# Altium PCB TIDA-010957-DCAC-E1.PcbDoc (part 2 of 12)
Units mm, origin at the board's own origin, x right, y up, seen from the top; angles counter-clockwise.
Board outline 300 x 300 mm, 4 copper layers (Top Layer, Layer 1, Layer 2, Bottom Layer), stack 1.787 mm thick; 1159 components, 619 nets, 3431 pads, 2942 vias.
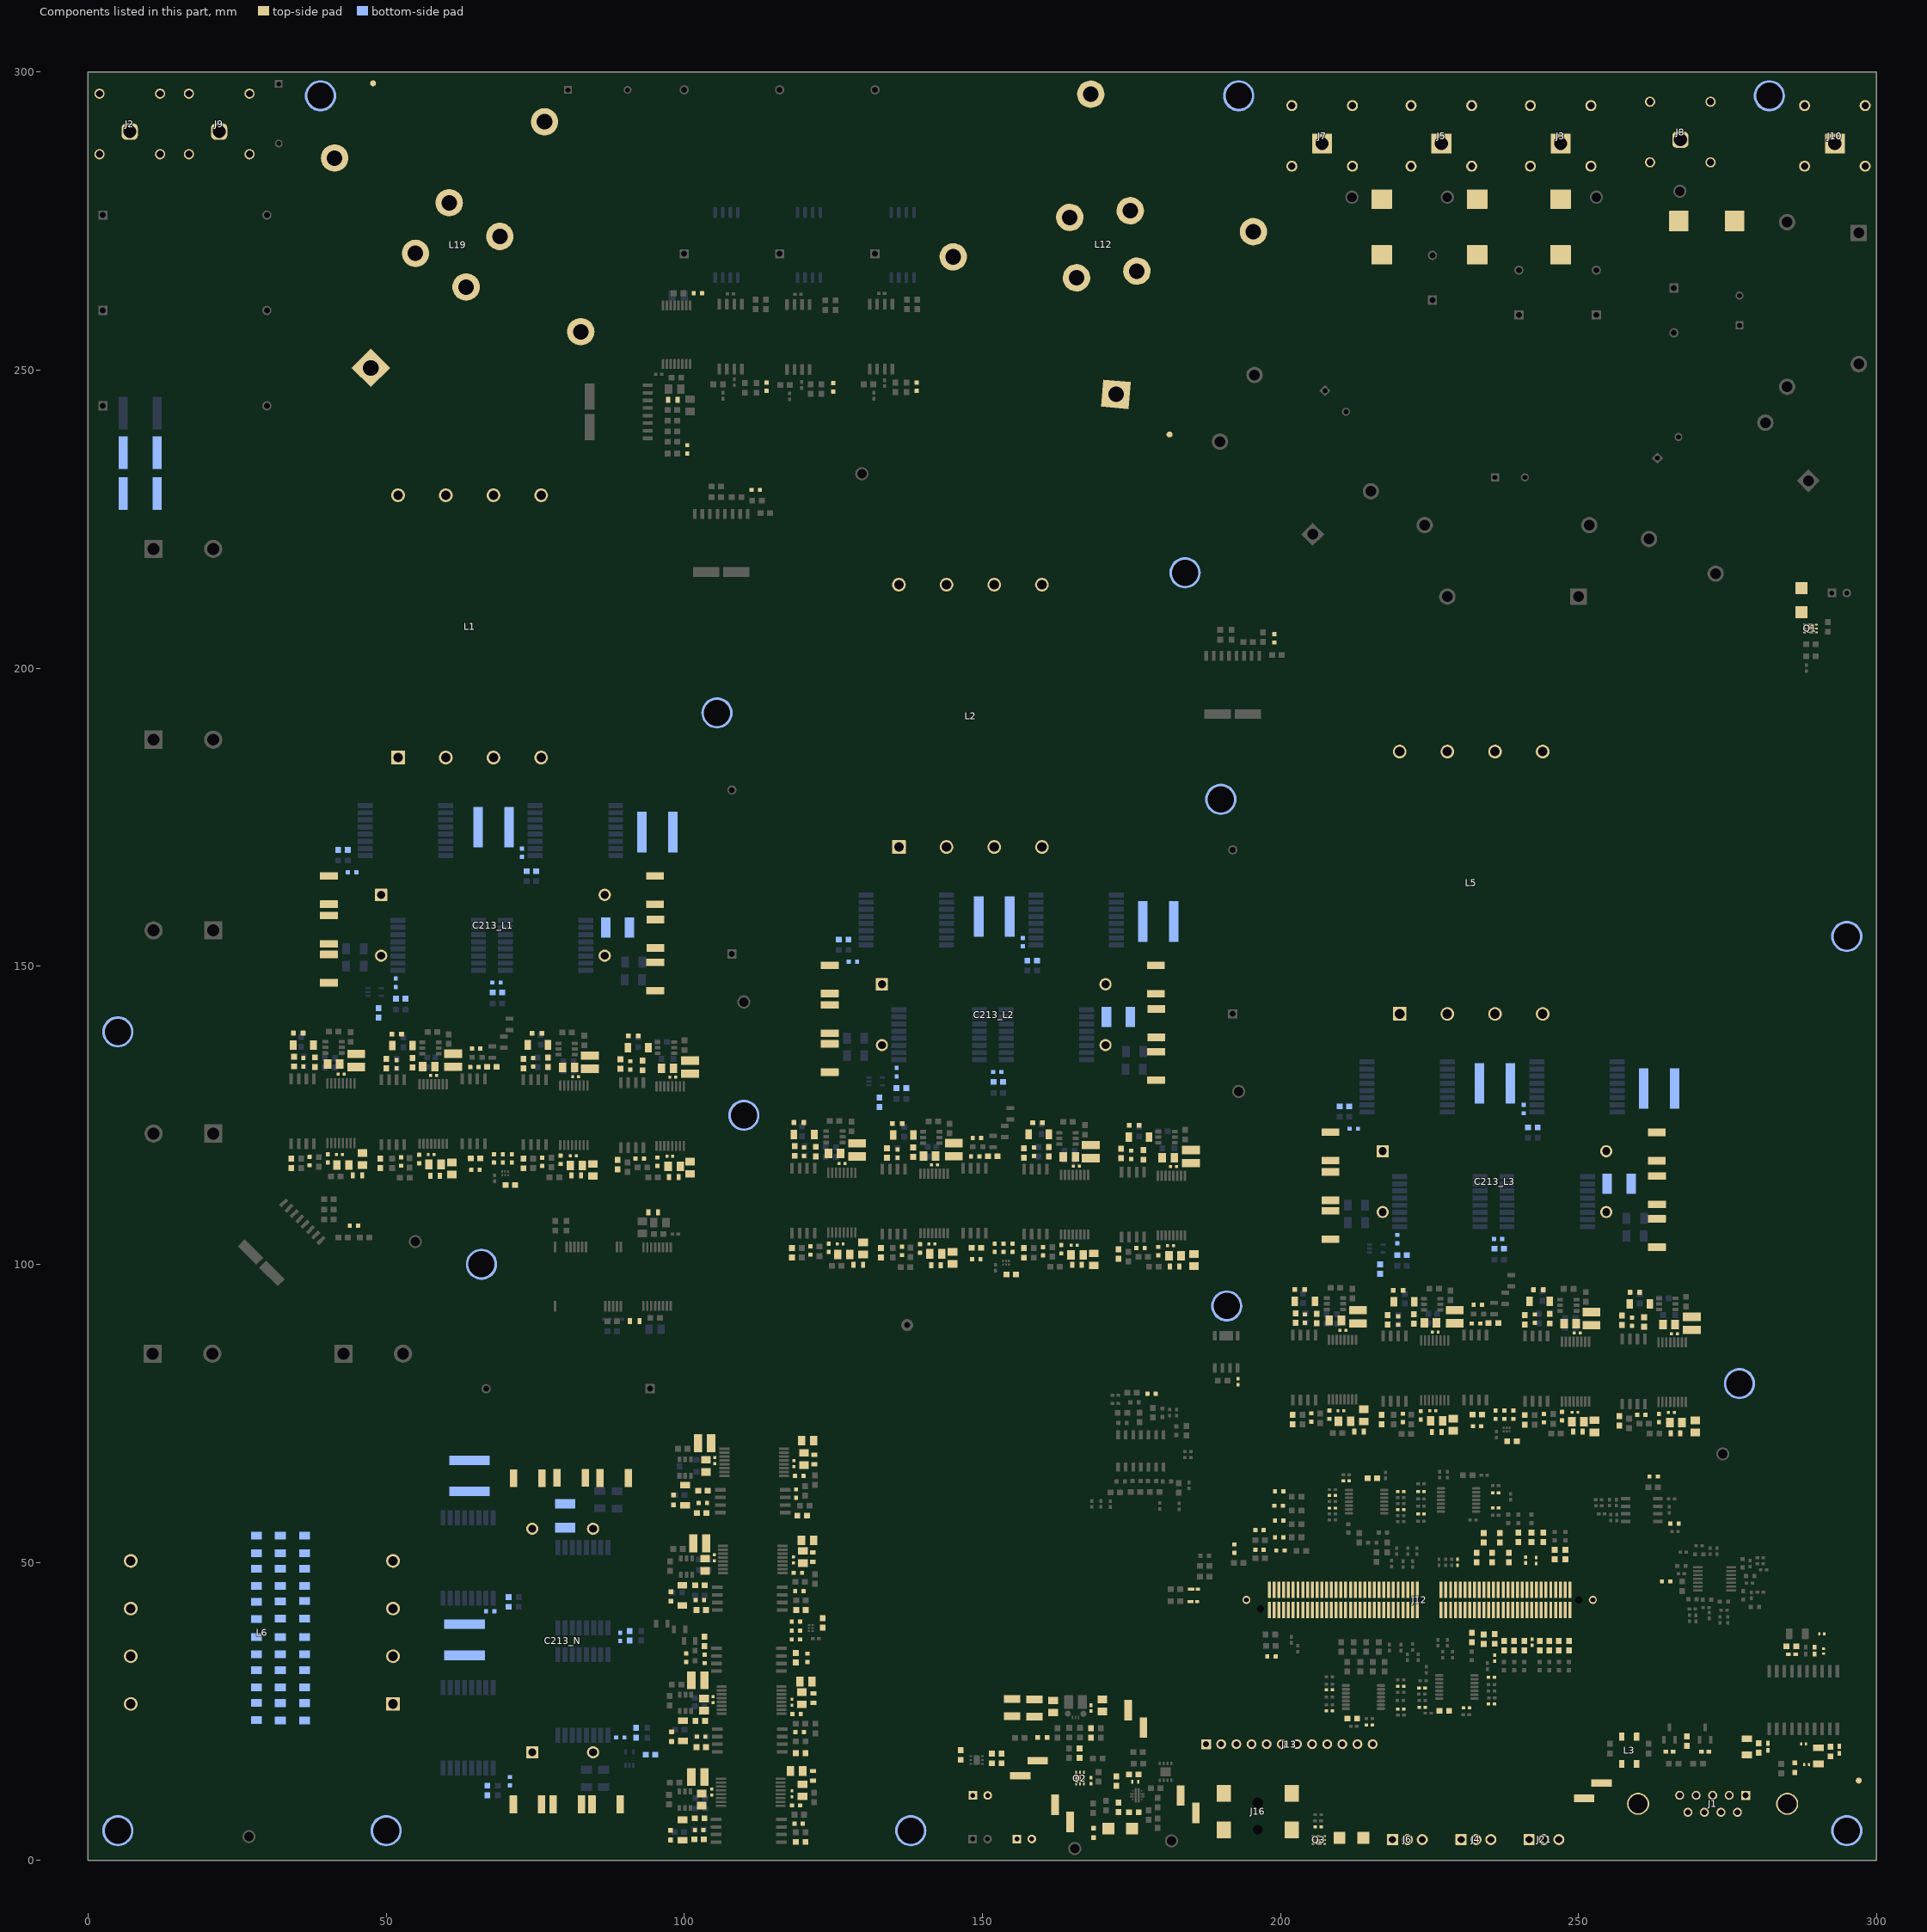
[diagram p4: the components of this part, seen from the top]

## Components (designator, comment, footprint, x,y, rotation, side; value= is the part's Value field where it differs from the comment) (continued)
C109 "GRM1555C1H101JA01D" 0402L 223.6,61.9 r180 top value=100pF
C110 "GRM1555C1H101JA01D" 0402L 223.6,58.15 r180 top value=100pF
C111 "GRM1555C1H101JA01D" 0402L 236.1,59.15 r0 top value=100pF
C112 "GRM1555C1H101JA01D" 0402L 236.1,61.65 r0 top value=100pF
C113 "06033C104JAT2A" 0603 215.4,64.1 r180 top value=0.1uF
C114 "06033C104JAT2A" 0603 212.066,23.781 r0 top value=0.1uF
C115 "GRM1555C1H101JA01D" 0402L 211.048,63.675 r180 top value=100pF
C116 "GRM1555C1H101JA01D" 0402L 208.7,61.2 r180 top value=100pF
C117 "GRM1555C1H101JA01D" 0402L 208.7,59.1 r180 top value=100pF
C118 "GRM1555C1H101JA01D" 0402L 220.2,58.85 r0 top value=100pF
C119 "GRM1555C1H101JA01D" 0402L 220.2,61.85 r0 top value=100pF
C120 "GRM1555C1H101JA01D" 0402L 214.9,22.7 r180 top value=100pF
C121 "GRM1555C1H101JA01D" 0402L 220.2,25.4 r0 top value=100pF
C122 "GRM1555C1H101JA01D" 0402L 220.2,29.2 r0 top value=100pF
C123 "GRM1555C1H101JA01D" 0402L 208.2,28.6 r180 top value=100pF
C124 "GRM1555C1H101JA01D" 0402L 208.2,25.1 r180 top value=100pF
C125 "06033C104JAT2A" 0603 227.5,25.1 r0 top value=0.1uF
C126 "GRM1555C1H101JA01D" 0402L 231.2,25.6 r180 top value=100pF
C127 "GRM1555C1H101JA01D" 0402L 235.393,26.25 r0 top value=100pF
C128 "GRM1555C1H101JA01D" 0402L 235.4,30.7 r0 top value=100pF
C129 "GRM1555C1H101JA01D" 0402L 223.75,28.9 r180 top value=100pF
C130 "GRM1555C1H101JA01D" 0402L 223.8,25.7 r180 top value=100pF
C131 "C1608X7R1V105K080AC" 0603 175.379,14.45 r180 top value=1uF
C132 "GCM155R71H104KE02D" 0402S 175.651,13.186 r180 top value=0.1uF
C133 "C1608X7R1V105K080AC" 0603 175.427,8.094 r180 top value=1uF
C134 "GRM188R72A272KA01D" 0603 172.851,8.9 r270 top value=2700pF
C135 "C0603X332K5RACTU" 0603 172.479,13.325 r90 top value=3300pF
C136 "GRM155R71E104KE14D" 0402L 168.232,13.384 r90 top value=0.1uF
C137 "GRM1885C2A220JA01D" 0603 168.207,21.396 r90 top value=22pF
C138 "06033C104JAT2A" 0603 153.2,17.1 r270 top value=0.1uF
C139 "GRM32ER71A476KE15L" 1210_270 158.733,25.569 r270 top value=47uF
C140 "GRM32ER71A476KE15L" 1210_270 154.983,25.615 r270 top value=47uF
C141 "EMK212BB7106KG-T" 0805_HV 170.133,25.994 r90 top value=10uF
C142 "GCM155R71H104KE02D" 0402L 168.207,25.544 r270 top value=0.1uF
C143 "GRM21BZ71A226ME15L" 0805_HV 161.883,25.819 r270 top value=22uF
C144 "EMK107BB7225KA-T" 0603 151.6,17.1 r270 top value=2.2uF
C145 "EMK107BB7225KA-T" 0603 146.35,17.677 r270 top value=2.2uF
C146 "C0603C103K4RACTU" 0603 166.32,17.971 r90 top value=0.01uF
C147 "GCM188R71C105KA64J" 0603 285.7,35.9 r180 top value=1uF
C148 "GRM155R71H103KA88D" 0402 285.8,34.6 r180 top value=0.01uF
C149 "GRM155R71E104KE14D" 0402 293.75,18.55 r270 top value=0.1uF
C150 "GCM188R71C105KA64J" 0603 292.25,18.25 r270 top value=1uF
C151 "CL31B106KBHNNNE" 1206_180L 290.25,17.55 r270 top value=10uF
C152 "GRM155R71E104KE14D" 0402 289.6,35.2 r90 top value=0.1uF
C153 "GRM155R71H103KA88D" 0402 281.75,19.05 r90 top value=0.01uF
C154 "GCM188R71C105KA64J" 0603 280.243,18.855 r90 top value=1uF
C155 "CL31B106KBHNNNE" 1206_180L 278.25,19.05 r90 top value=10uF
C156 "C1005C0G1H680J050BA" 0402 265.25,18.25 r0 top value=68pF
C157 "C0603X472K5RACTU" 0603 268.2,20 r270 top value=4700pF
C158 "C1005C0G1H680J050BA" 0402 271.25,18.25 r180 top value=68pF
C159 "CGA3E2C0G1H331J080AA" FP-CGA3E2C0G1H331J080AA_0603-MFG 199.8,61.9 r0 top value=330pF
C160 "CGA3E2C0G1H331J080AA" FP-CGA3E2C0G1H331J080AA_0603-MFG 199.7,59.5 r0 top value=330pF
C161 "CGA3E2C0G1H331J080AA" FP-CGA3E2C0G1H331J080AA_0603-MFG 199.8,57 r0 top value=330pF
C162 "CGA3E2C0G1H331J080AA" FP-CGA3E2C0G1H331J080AA_0603-MFG 199.8,54.2 r0 top value=330pF
C186_L1 "06033C104JAT2A" 0603 88.825,116.73 r270 top value=0.1uF (schematic designator C186)
C186_L2 "06033C104JAT2A" 0603 172.825,101.73 r270 top value=0.1uF (schematic designator C186)
C186_L3 "06033C104JAT2A" 0603 256.825,73.73 r270 top value=0.1uF (schematic designator C186)
C186_N "06033C104JAT2A" 0603 119.77,57.825 r0 top value=0.1uF (schematic designator C186)
C187_L1 "06033C104JAT2A" 0603 89.3,133.594 r90 top value=0.1uF (schematic designator C187)
C187_L2 "06033C104JAT2A" 0603 173.3,118.594 r90 top value=0.1uF (schematic designator C187)
C187_L3 "06033C104JAT2A" 0603 257.3,90.594 r90 top value=0.1uF (schematic designator C187)
C187_N "06033C104JAT2A" 0603 102.906,58.3 r180 top value=0.1uF (schematic designator C187)
C188_L1 "CGA3E2C0G1H331J080AA" FP-CGA3E2C0G1H331J080AA_0603-MFG 72.801,169.047 r270 bottom value=330pF (schematic designator C188)
C188_L2 "CGA3E2C0G1H331J080AA" FP-CGA3E2C0G1H331J080AA_0603-MFG 156.801,154.047 r270 bottom value=330pF (schematic designator C188)
C188_L3 "CGA3E2C0G1H331J080AA" FP-CGA3E2C0G1H331J080AA_0603-MFG 240.801,126.047 r270 bottom value=330pF (schematic designator C188)
C188_N "CGA3E2C0G1H331J080AA" FP-CGA3E2C0G1H331J080AA_0603-MFG 67.453,41.801 r0 bottom value=330pF (schematic designator C188)
C189_L1 "CGA3E2C0G1H331J080AA" FP-CGA3E2C0G1H331J080AA_0603-MFG 90.967,133.366 r270 top value=330pF (schematic designator C189)
C189_L2 "CGA3E2C0G1H331J080AA" FP-CGA3E2C0G1H331J080AA_0603-MFG 174.967,118.366 r270 top value=330pF (schematic designator C189)
C189_L3 "CGA3E2C0G1H331J080AA" FP-CGA3E2C0G1H331J080AA_0603-MFG 258.967,90.366 r270 top value=330pF (schematic designator C189)
C189_N "CGA3E2C0G1H331J080AA" FP-CGA3E2C0G1H331J080AA_0603-MFG 103.134,59.967 r0 top value=330pF (schematic designator C189)
C190_L1 "06033C104JAT2A" 0603 74.351,165.957 r180 bottom value=0.1uF (schematic designator C190)
C190_L2 "06033C104JAT2A" 0603 158.351,150.957 r180 bottom value=0.1uF (schematic designator C190)
C190_L3 "06033C104JAT2A" 0603 242.351,122.957 r180 bottom value=0.1uF (schematic designator C190)
C190_N "06033C104JAT2A" 0603 70.543,43.351 r270 bottom value=0.1uF (schematic designator C190)
C191_L1 "CGA3E2C0G1H331J080AA" FP-CGA3E2C0G1H331J080AA_0603-MFG 92.538,117.738 r180 top value=330pF (schematic designator C191)
C191_L2 "CGA3E2C0G1H331J080AA" FP-CGA3E2C0G1H331J080AA_0603-MFG 176.538,102.738 r180 top value=330pF (schematic designator C191)
C191_L3 "CGA3E2C0G1H331J080AA" FP-CGA3E2C0G1H331J080AA_0603-MFG 260.538,74.738 r180 top value=330pF (schematic designator C191)
C191_N "CGA3E2C0G1H331J080AA" FP-CGA3E2C0G1H331J080AA_0603-MFG 118.762,61.538 r270 top value=330pF (schematic designator C191)
C192_L1 "GRT31CR61H106KE01L" 1206_180 92.275,136.345 r180 top value=10uF (schematic designator C192)
C192_L2 "GRT31CR61H106KE01L" 1206_180 176.275,121.345 r180 top value=10uF (schematic designator C192)
C192_L3 "GRT31CR61H106KE01L" 1206_180 260.275,93.345 r180 top value=10uF (schematic designator C192)
C192_N "GRT31CR61H106KE01L" 1206_180 100.155,61.275 r270 top value=10uF (schematic designator C192)
C193_L1 "885012205063" WCAP-CSGP_0402_L1W0.5H0.5 98.088,131.367 r0 top (schematic designator C193)
C193_L2 "885012205063" WCAP-CSGP_0402_L1W0.5H0.5 182.088,116.367 r0 top (schematic designator C193)
C193_L3 "885012205063" WCAP-CSGP_0402_L1W0.5H0.5 266.088,88.367 r0 top (schematic designator C193)
C193_N "885012205063" WCAP-CSGP_0402_L1W0.5H0.5 105.133,67.088 r90 top (schematic designator C193)
C194_L1 "GRM21BZ71A226ME15L" 0805_HV 97.188,132.869 r180 top value=22uF (schematic designator C194)
C194_L2 "GRM21BZ71A226ME15L" 0805_HV 181.188,117.869 r180 top value=22uF (schematic designator C194)
C194_L3 "GRM21BZ71A226ME15L" 0805_HV 265.188,89.869 r180 top value=22uF (schematic designator C194)
C194_N "GRM21BZ71A226ME15L" 0805_HV 103.631,66.188 r270 top value=22uF (schematic designator C194)
C195_L1 "06033C104JAT2A" 0603 93,133.348 r270 top value=0.1uF (schematic designator C195)
C195_L2 "06033C104JAT2A" 0603 177,118.348 r270 top value=0.1uF (schematic designator C195)
C195_L3 "06033C104JAT2A" 0603 261,90.348 r270 top value=0.1uF (schematic designator C195)
C195_N "06033C104JAT2A" 0603 103.152,62 r0 top value=0.1uF (schematic designator C195)
C196_L1 "CGA3E2C0G1H331J080AA" FP-CGA3E2C0G1H331J080AA_0603-MFG 95.497,117.205 r90 top value=330pF (schematic designator C196)
C196_L2 "CGA3E2C0G1H331J080AA" FP-CGA3E2C0G1H331J080AA_0603-MFG 179.497,102.205 r90 top value=330pF (schematic designator C196)
C196_L3 "CGA3E2C0G1H331J080AA" FP-CGA3E2C0G1H331J080AA_0603-MFG 263.497,74.205 r90 top value=330pF (schematic designator C196)
C196_N "CGA3E2C0G1H331J080AA" FP-CGA3E2C0G1H331J080AA_0603-MFG 119.295,64.497 r180 top value=330pF (schematic designator C196)
C197_L1 "GRM21BZ71A226ME15L" 0805_HV 101,116.188 r90 top value=22uF (schematic designator C197)
C197_L2 "GRM21BZ71A226ME15L" 0805_HV 185.5,100.7 r90 top value=22uF (schematic designator C197)
C197_L3 "GRM21BZ71A226ME15L" 0805_HV 269.6,72.8 r90 top value=22uF (schematic designator C197)
C197_N "GRM21BZ71A226ME15L" 0805_HV 120.7,70.4 r180 top value=22uF (schematic designator C197)
C198_L1 "GRM21BZ71A226ME15L" 0805_HV 98.338,116.43 r0 top value=22uF (schematic designator C198)
C198_L2 "GRM21BZ71A226ME15L" 0805_HV 182.338,101.43 r0 top value=22uF (schematic designator C198)
C198_L3 "GRM21BZ71A226ME15L" 0805_HV 266.338,73.43 r0 top value=22uF (schematic designator C198)
C198_N "GRM21BZ71A226ME15L" 0805_HV 120.07,67.338 r90 top value=22uF (schematic designator C198)
C199_L1 "885012205051" WCAP-CSGP_0402_L1W0.5H0.5 97.588,118.13 r180 top (schematic designator C199)
C199_L2 "885012205051" WCAP-CSGP_0402_L1W0.5H0.5 181.588,103.13 r180 top (schematic designator C199)
C199_L3 "885012205051" WCAP-CSGP_0402_L1W0.5H0.5 265.588,75.13 r180 top (schematic designator C199)
C199_N "885012205051" WCAP-CSGP_0402_L1W0.5H0.5 118.37,66.588 r270 top (schematic designator C199)
C200_L1 "06033C104JAT2A" 0603 73.005,116.908 r270 top value=0.1uF (schematic designator C200)
C200_L2 "06033C104JAT2A" 0603 157.005,101.908 r270 top value=0.1uF (schematic designator C200)
C200_L3 "06033C104JAT2A" 0603 241.005,73.908 r270 top value=0.1uF (schematic designator C200)
C200_N "06033C104JAT2A" 0603 119.592,42.005 r0 top value=0.1uF (schematic designator C200)
C201_L1 "06033C104JAT2A" 0603 73.005,133.666 r90 top value=0.1uF (schematic designator C201)
C201_L2 "06033C104JAT2A" 0603 157.005,118.666 r90 top value=0.1uF (schematic designator C201)
C201_L3 "06033C104JAT2A" 0603 241.005,90.666 r90 top value=0.1uF (schematic designator C201)
C201_N "06033C104JAT2A" 0603 102.834,42.005 r180 top value=0.1uF (schematic designator C201)
C202_L1 "CGA3E2C0G1H331J080AA" FP-CGA3E2C0G1H331J080AA_0603-MFG 68.507,147.25 r0 bottom value=330pF (schematic designator C202)
C202_L2 "CGA3E2C0G1H331J080AA" FP-CGA3E2C0G1H331J080AA_0603-MFG 152.507,132.25 r0 bottom value=330pF (schematic designator C202)
C202_L3 "CGA3E2C0G1H331J080AA" FP-CGA3E2C0G1H331J080AA_0603-MFG 236.507,104.25 r0 bottom value=330pF (schematic designator C202)
C202_N "CGA3E2C0G1H331J080AA" FP-CGA3E2C0G1H331J080AA_0603-MFG 89.25,37.507 r90 bottom value=330pF (schematic designator C202)
C203_L1 "CGA3E2C0G1H331J080AA" FP-CGA3E2C0G1H331J080AA_0603-MFG 74.66,133.882 r270 top value=330pF (schematic designator C203)
C203_L2 "CGA3E2C0G1H331J080AA" FP-CGA3E2C0G1H331J080AA_0603-MFG 158.66,118.882 r270 top value=330pF (schematic designator C203)
C203_L3 "CGA3E2C0G1H331J080AA" FP-CGA3E2C0G1H331J080AA_0603-MFG 242.66,90.882 r270 top value=330pF (schematic designator C203)
C203_N "CGA3E2C0G1H331J080AA" FP-CGA3E2C0G1H331J080AA_0603-MFG 102.618,43.66 r0 top value=330pF (schematic designator C203)
C204_L1 "06033C104JAT2A" 0603 68.682,145.625 r180 bottom value=0.1uF (schematic designator C204)
C204_L2 "06033C104JAT2A" 0603 152.682,130.625 r180 bottom value=0.1uF (schematic designator C204)
C204_L3 "06033C104JAT2A" 0603 236.682,102.625 r180 bottom value=0.1uF (schematic designator C204)
C204_N "06033C104JAT2A" 0603 90.875,37.682 r270 bottom value=0.1uF (schematic designator C204)
C205_L1 "CGA3E2C0G1H331J080AA" FP-CGA3E2C0G1H331J080AA_0603-MFG 76.18,117.18 r90 top value=330pF (schematic designator C205)
C205_L2 "CGA3E2C0G1H331J080AA" FP-CGA3E2C0G1H331J080AA_0603-MFG 160.18,102.18 r90 top value=330pF (schematic designator C205)
C205_L3 "CGA3E2C0G1H331J080AA" FP-CGA3E2C0G1H331J080AA_0603-MFG 244.18,74.18 r90 top value=330pF (schematic designator C205)
C205_N "CGA3E2C0G1H331J080AA" FP-CGA3E2C0G1H331J080AA_0603-MFG 119.32,45.18 r180 top value=330pF (schematic designator C205)
C206_L1 "CGA3E2C0G1H331J080AA" FP-CGA3E2C0G1H331J080AA_0603-MFG 68.075,117.763 r270 top value=330pF (schematic designator C206)
C206_L2 "CGA3E2C0G1H331J080AA" FP-CGA3E2C0G1H331J080AA_0603-MFG 152.075,102.763 r270 top value=330pF (schematic designator C206)
C206_L3 "CGA3E2C0G1H331J080AA" FP-CGA3E2C0G1H331J080AA_0603-MFG 236.075,74.763 r270 top value=330pF (schematic designator C206)
C206_N "CGA3E2C0G1H331J080AA" FP-CGA3E2C0G1H331J080AA_0603-MFG 118.737,37.075 r0 top value=330pF (schematic designator C206)
C207_L1 "CGA3E2C0G1H331J080AA" FP-CGA3E2C0G1H331J080AA_0603-MFG 71.084,117.763 r270 top value=330pF (schematic designator C207)
C207_L2 "CGA3E2C0G1H331J080AA" FP-CGA3E2C0G1H331J080AA_0603-MFG 155.084,102.763 r270 top value=330pF (schematic designator C207)
C207_L3 "CGA3E2C0G1H331J080AA" FP-CGA3E2C0G1H331J080AA_0603-MFG 239.084,74.763 r270 top value=330pF (schematic designator C207)
C207_N "CGA3E2C0G1H331J080AA" FP-CGA3E2C0G1H331J080AA_0603-MFG 118.737,40.084 r0 top value=330pF (schematic designator C207)
C208_L1 "GRT31CR61H106KE01L" 1206_180 75.455,136.8 r180 top value=10uF (schematic designator C208)
C208_L2 "GRT31CR61H106KE01L" 1206_180 159.455,121.8 r180 top value=10uF (schematic designator C208)
C208_L3 "GRT31CR61H106KE01L" 1206_180 243.455,93.8 r180 top value=10uF (schematic designator C208)
C208_N "GRT31CR61H106KE01L" 1206_180 99.7,44.455 r270 top value=10uF (schematic designator C208)
C209_L1 "CGA3E2C0G1H331J080AA" FP-CGA3E2C0G1H331J080AA_0603-MFG 69.566,117.763 r270 top value=330pF (schematic designator C209)
C209_L2 "CGA3E2C0G1H331J080AA" FP-CGA3E2C0G1H331J080AA_0603-MFG 153.566,102.763 r270 top value=330pF (schematic designator C209)
C209_L3 "CGA3E2C0G1H331J080AA" FP-CGA3E2C0G1H331J080AA_0603-MFG 237.566,74.763 r270 top value=330pF (schematic designator C209)
C209_N "CGA3E2C0G1H331J080AA" FP-CGA3E2C0G1H331J080AA_0603-MFG 118.737,38.566 r0 top value=330pF (schematic designator C209)
C210_L1 "885012205063" WCAP-CSGP_0402_L1W0.5H0.5 81.794,131.467 r0 top (schematic designator C210)
C210_L2 "885012205063" WCAP-CSGP_0402_L1W0.5H0.5 165.794,116.467 r0 top (schematic designator C210)
C210_L3 "885012205063" WCAP-CSGP_0402_L1W0.5H0.5 249.794,88.467 r0 top (schematic designator C210)
C210_N "885012205063" WCAP-CSGP_0402_L1W0.5H0.5 105.033,50.794 r90 top (schematic designator C210)
C211_L1 "GRM21BZ71A226ME15L" 0805_HV 80.6,133.023 r180 top value=22uF (schematic designator C211)
C211_L2 "GRM21BZ71A226ME15L" 0805_HV 164.6,118.023 r180 top value=22uF (schematic designator C211)
C211_L3 "GRM21BZ71A226ME15L" 0805_HV 248.6,90.023 r180 top value=22uF (schematic designator C211)
C211_N "GRM21BZ71A226ME15L" 0805_HV 103.477,49.6 r270 top value=22uF (schematic designator C211)
C212_L1 "06033C104JAT2A" 0603 77.155,133.871 r270 top value=0.1uF (schematic designator C212)
C212_L2 "06033C104JAT2A" 0603 161.155,118.871 r270 top value=0.1uF (schematic designator C212)
C212_L3 "06033C104JAT2A" 0603 245.155,90.871 r270 top value=0.1uF (schematic designator C212)
C212_N "06033C104JAT2A" 0603 102.629,46.155 r0 top value=0.1uF (schematic designator C212)
C213_L1 "B32676G6126K000" FP-B32676G6126K000_RADIAL-MFG 67.911,156.866 r0 top value=12µF (schematic designator C213)
C213_L2 "B32676G6126K000" FP-B32676G6126K000_RADIAL-MFG 151.911,141.866 r0 top value=12µF (schematic designator C213)
C213_L3 "B32676G6126K000" FP-B32676G6126K000_RADIAL-MFG 235.911,113.866 r0 top value=12µF (schematic designator C213)
C213_N "B32676G6126K000" FP-B32676G6126K000_RADIAL-MFG 79.609,36.886 r90 top locked value=12µF (schematic designator C213)
C215_L1 "C1812W104KDRACTU" 1812_254 88.825,156.5 r180 bottom value=0.1uF (schematic designator C215)
C215_L2 "C1812W104KDRACTU" 1812_254 172.825,141.5 r180 bottom value=0.1uF (schematic designator C215)
C215_L3 "C1812W104KDRACTU" 1812_254 256.825,113.5 r180 bottom value=0.1uF (schematic designator C215)
C215_N "C1812W104KDRACTU" 1812_254 80,57.825 r270 bottom value=0.1uF (schematic designator C215)
C216_L1 "C2225C104KFRACTU" 2225 68,173.35 r180 bottom value=0.1uF (schematic designator C216)
C216_L2 "C2225C104KFRACTU" 2225 152,158.35 r180 bottom value=0.1uF (schematic designator C216)
C216_L3 "C2225C104KFRACTU" 2225 236,130.35 r180 bottom value=0.1uF (schematic designator C216)
C216_N "C2225C104KFRACTU" 2225 63.15,37 r270 bottom value=0.1uF (schematic designator C216)
C217_L1 "C2225C104KFRACTU" 2225 95.5,172.5 r0 bottom value=0.1uF (schematic designator C217)
C217_L2 "C2225C104KFRACTU" 2225 179.5,157.5 r0 bottom value=0.1uF (schematic designator C217)
C217_L3 "C2225C104KFRACTU" 2225 263.5,129.5 r0 bottom value=0.1uF (schematic designator C217)
C217_N "C2225C104KFRACTU" 2225 64,64.5 r90 bottom value=0.1uF (schematic designator C217)
C219_L1 "CGA3E2C0G1H331J080AA" FP-CGA3E2C0G1H331J080AA_0603-MFG 79.25,117.53 r90 top value=330pF (schematic designator C219)
C219_L2 "CGA3E2C0G1H331J080AA" FP-CGA3E2C0G1H331J080AA_0603-MFG 163.25,102.53 r90 top value=330pF (schematic designator C219)
C219_L3 "CGA3E2C0G1H331J080AA" FP-CGA3E2C0G1H331J080AA_0603-MFG 247.25,74.53 r90 top value=330pF (schematic designator C219)
C219_N "CGA3E2C0G1H331J080AA" FP-CGA3E2C0G1H331J080AA_0603-MFG 119.07,48.25 r180 top value=330pF (schematic designator C219)
C220_L1 "GRM21BZ71A226ME15L" 0805_HV 84.675,115.817 r90 top value=22uF (schematic designator C220)
C220_L2 "GRM21BZ71A226ME15L" 0805_HV 168.675,100.817 r90 top value=22uF (schematic designator C220)
C220_L3 "GRM21BZ71A226ME15L" 0805_HV 252.675,72.817 r90 top value=22uF (schematic designator C220)
C220_N "GRM21BZ71A226ME15L" 0805_HV 120.683,53.675 r180 top value=22uF (schematic designator C220)
C221_L1 "GRM21BZ71A226ME15L" 0805_HV 81.9,116.588 r0 top value=22uF (schematic designator C221)
C221_L2 "GRM21BZ71A226ME15L" 0805_HV 165.9,101.588 r0 top value=22uF (schematic designator C221)
C221_L3 "GRM21BZ71A226ME15L" 0805_HV 249.9,73.588 r0 top value=22uF (schematic designator C221)
C221_N "GRM21BZ71A226ME15L" 0805_HV 119.912,50.9 r90 top value=22uF (schematic designator C221)
C222_L1 "885012205051" WCAP-CSGP_0402_L1W0.5H0.5 81.394,118.182 r180 top (schematic designator C222)
C222_L2 "885012205051" WCAP-CSGP_0402_L1W0.5H0.5 165.394,103.182 r180 top (schematic designator C222)
C222_L3 "885012205051" WCAP-CSGP_0402_L1W0.5H0.5 249.394,75.182 r180 top (schematic designator C222)
C222_N "885012205051" WCAP-CSGP_0402_L1W0.5H0.5 118.318,50.394 r270 top (schematic designator C222)
C223_L1 "06033C104JAT2A" 0603 70.831,113.292 r0 top value=0.1uF (schematic designator C223)
C223_L2 "06033C104JAT2A" 0603 154.831,98.292 r0 top value=0.1uF (schematic designator C223)
C223_L3 "06033C104JAT2A" 0603 238.831,70.292 r0 top value=0.1uF (schematic designator C223)
C223_N "06033C104JAT2A" 0603 123.208,39.831 r90 top value=0.1uF (schematic designator C223)
C224_L1 "06033C104JAT2A" 0603 49,116.955 r270 top value=0.1uF (schematic designator C224)
C224_L2 "06033C104JAT2A" 0603 133,101.955 r270 top value=0.1uF (schematic designator C224)
C224_L3 "06033C104JAT2A" 0603 217,73.955 r270 top value=0.1uF (schematic designator C224)
C224_N "06033C104JAT2A" 0603 119.545,18 r0 top value=0.1uF (schematic designator C224)
C225_L1 "06033C104JAT2A" 0603 50.008,133.666 r90 top value=0.1uF (schematic designator C225)
C225_L2 "06033C104JAT2A" 0603 134.008,118.666 r90 top value=0.1uF (schematic designator C225)
C225_L3 "06033C104JAT2A" 0603 218.008,90.666 r90 top value=0.1uF (schematic designator C225)
C225_N "06033C104JAT2A" 0603 102.834,19.008 r180 top value=0.1uF (schematic designator C225)
C226_L1 "CGA3E2C0G1H331J080AA" FP-CGA3E2C0G1H331J080AA_0603-MFG 51.622,147.225 r90 bottom value=330pF (schematic designator C226)
C226_L2 "CGA3E2C0G1H331J080AA" FP-CGA3E2C0G1H331J080AA_0603-MFG 135.622,132.225 r90 bottom value=330pF (schematic designator C226)
C226_L3 "CGA3E2C0G1H331J080AA" FP-CGA3E2C0G1H331J080AA_0603-MFG 219.622,104.225 r90 bottom value=330pF (schematic designator C226)
C226_N "CGA3E2C0G1H331J080AA" FP-CGA3E2C0G1H331J080AA_0603-MFG 89.275,20.622 r180 bottom value=330pF (schematic designator C226)
C227_L1 "CGA3E2C0G1H331J080AA" FP-CGA3E2C0G1H331J080AA_0603-MFG 51.764,133.566 r270 top value=330pF (schematic designator C227)
C227_L2 "CGA3E2C0G1H331J080AA" FP-CGA3E2C0G1H331J080AA_0603-MFG 135.764,118.566 r270 top value=330pF (schematic designator C227)
C227_L3 "CGA3E2C0G1H331J080AA" FP-CGA3E2C0G1H331J080AA_0603-MFG 219.764,90.566 r270 top value=330pF (schematic designator C227)
C227_N "CGA3E2C0G1H331J080AA" FP-CGA3E2C0G1H331J080AA_0603-MFG 102.834,20.764 r0 top value=330pF (schematic designator C227)
C228_L1 "06033C104JAT2A" 0603 48.723,142.175 r270 bottom value=0.1uF (schematic designator C228)
C228_L2 "06033C104JAT2A" 0603 132.723,127.175 r270 bottom value=0.1uF (schematic designator C228)
C228_L3 "06033C104JAT2A" 0603 216.723,99.175 r270 bottom value=0.1uF (schematic designator C228)
C228_N "06033C104JAT2A" 0603 94.325,17.723 r0 bottom value=0.1uF (schematic designator C228)
C229_L1 "06033C104JAT2A" 0603 52.422,144.55 r180 bottom value=0.1uF (schematic designator C229)
C229_L2 "06033C104JAT2A" 0603 136.422,129.55 r180 bottom value=0.1uF (schematic designator C229)
C229_L3 "06033C104JAT2A" 0603 220.422,101.55 r180 bottom value=0.1uF (schematic designator C229)
C229_N "06033C104JAT2A" 0603 91.95,21.422 r270 bottom value=0.1uF (schematic designator C229)
C230_L1 "CGA3E2C0G1H331J080AA" FP-CGA3E2C0G1H331J080AA_0603-MFG 196.5,55.4 r180 top value=330pF (schematic designator C230)
C230_L2 "CGA3E2C0G1H331J080AA" FP-CGA3E2C0G1H331J080AA_0603-MFG 200,52 r0 top value=330pF (schematic designator C230)
C230_L3 "CGA3E2C0G1H331J080AA" FP-CGA3E2C0G1H331J080AA_0603-MFG 196.486,52.119 r180 top value=330pF (schematic designator C230)
C230_N "CGA3E2C0G1H331J080AA" FP-CGA3E2C0G1H331J080AA_0603-MFG 192.3,52.3 r270 top value=330pF (schematic designator C230)
C231_L1 "CGA3E2C0G1H331J080AA" FP-CGA3E2C0G1H331J080AA_0603-MFG 52.528,117.234 r90 top value=330pF (schematic designator C231)
C231_L2 "CGA3E2C0G1H331J080AA" FP-CGA3E2C0G1H331J080AA_0603-MFG 136.528,102.234 r90 top value=330pF (schematic designator C231)
C231_L3 "CGA3E2C0G1H331J080AA" FP-CGA3E2C0G1H331J080AA_0603-MFG 220.528,74.234 r90 top value=330pF (schematic designator C231)
C231_N "CGA3E2C0G1H331J080AA" FP-CGA3E2C0G1H331J080AA_0603-MFG 119.366,21.528 r180 top value=330pF (schematic designator C231)
C232_L1 "GRT31CR61H106KE01L" 1206_180 52.729,136.708 r180 top value=10uF (schematic designator C232)
C232_L2 "GRT31CR61H106KE01L" 1206_180 136.729,121.708 r180 top value=10uF (schematic designator C232)
C232_L3 "GRT31CR61H106KE01L" 1206_180 220.729,93.708 r180 top value=10uF (schematic designator C232)
C232_N "GRT31CR61H106KE01L" 1206_180 99.792,21.729 r270 top value=10uF (schematic designator C232)
C233_L1 "885012205063" WCAP-CSGP_0402_L1W0.5H0.5 57.958,131.657 r0 top (schematic designator C233)
C233_L2 "885012205063" WCAP-CSGP_0402_L1W0.5H0.5 141.958,116.657 r0 top (schematic designator C233)
C233_L3 "885012205063" WCAP-CSGP_0402_L1W0.5H0.5 225.958,88.657 r0 top (schematic designator C233)
C233_N "885012205063" WCAP-CSGP_0402_L1W0.5H0.5 104.843,26.958 r90 top (schematic designator C233)
C234_L1 "GRM21BZ71A226ME15L" 0805_HV 57.158,133.182 r180 top value=22uF (schematic designator C234)
C234_L2 "GRM21BZ71A226ME15L" 0805_HV 141.158,118.182 r180 top value=22uF (schematic designator C234)
C234_L3 "GRM21BZ71A226ME15L" 0805_HV 225.158,90.182 r180 top value=22uF (schematic designator C234)
C234_N "GRM21BZ71A226ME15L" 0805_HV 103.318,26.158 r270 top value=22uF (schematic designator C234)
C235_L1 "06033C104JAT2A" 0603 54.404,133.823 r270 top value=0.1uF (schematic designator C235)
C235_L2 "06033C104JAT2A" 0603 138.404,118.823 r270 top value=0.1uF (schematic designator C235)
C235_L3 "06033C104JAT2A" 0603 222.404,90.823 r270 top value=0.1uF (schematic designator C235)
C235_N "06033C104JAT2A" 0603 102.677,23.404 r0 top value=0.1uF (schematic designator C235)
C236_L1 "CGA3E2C0G1H331J080AA" FP-CGA3E2C0G1H331J080AA_0603-MFG 55.541,117.655 r90 top value=330pF (schematic designator C236)
C236_L2 "CGA3E2C0G1H331J080AA" FP-CGA3E2C0G1H331J080AA_0603-MFG 139.541,102.655 r90 top value=330pF (schematic designator C236)
C236_L3 "CGA3E2C0G1H331J080AA" FP-CGA3E2C0G1H331J080AA_0603-MFG 223.541,74.655 r90 top value=330pF (schematic designator C236)
C236_N "CGA3E2C0G1H331J080AA" FP-CGA3E2C0G1H331J080AA_0603-MFG 118.845,24.541 r180 top value=330pF (schematic designator C236)
C237_L1 "GRM21BZ71A226ME15L" 0805_HV 61,116.08 r90 top value=22uF (schematic designator C237)
C237_L2 "GRM21BZ71A226ME15L" 0805_HV 145,101.08 r90 top value=22uF (schematic designator C237)
C237_L3 "GRM21BZ71A226ME15L" 0805_HV 229,73.08 r90 top value=22uF (schematic designator C237)
C237_N "GRM21BZ71A226ME15L" 0805_HV 120.42,30 r180 top value=22uF (schematic designator C237)
C238_L1 "GRM21BZ71A226ME15L" 0805_HV 58.198,116.755 r0 top value=22uF (schematic designator C238)
C238_L2 "GRM21BZ71A226ME15L" 0805_HV 142.198,101.755 r0 top value=22uF (schematic designator C238)
C238_L3 "GRM21BZ71A226ME15L" 0805_HV 226.198,73.755 r0 top value=22uF (schematic designator C238)
C238_N "GRM21BZ71A226ME15L" 0805_HV 119.745,27.198 r90 top value=22uF (schematic designator C238)
C239_L1 "885012205051" WCAP-CSGP_0402_L1W0.5H0.5 57.56,118.432 r180 top (schematic designator C239)
C239_L2 "885012205051" WCAP-CSGP_0402_L1W0.5H0.5 141.56,103.432 r180 top (schematic designator C239)
C239_L3 "885012205051" WCAP-CSGP_0402_L1W0.5H0.5 225.56,75.432 r180 top (schematic designator C239)
C239_N "885012205051" WCAP-CSGP_0402_L1W0.5H0.5 118.068,26.56 r270 top (schematic designator C239)
C240_L1 "06033C104JAT2A" 0603 65,117.786 r180 top value=0.1uF (schematic designator C240)
C240_L2 "06033C104JAT2A" 0603 149,102.786 r180 top value=0.1uF (schematic designator C240)
C240_L3 "06033C104JAT2A" 0603 233,74.786 r180 top value=0.1uF (schematic designator C240)
C240_N "06033C104JAT2A" 0603 118.714,34 r270 top value=0.1uF (schematic designator C240)
C241_L1 "06033C104JAT2A" 0603 67.725,133.116 r0 top value=0.1uF (schematic designator C241)
C241_L2 "06033C104JAT2A" 0603 151.725,118.116 r0 top value=0.1uF (schematic designator C241)
C241_L3 "06033C104JAT2A" 0603 235.725,90.116 r0 top value=0.1uF (schematic designator C241)
C241_N "06033C104JAT2A" 0603 103.384,36.725 r90 top value=0.1uF (schematic designator C241)
C242_L1 "CGA3E2C0G1H331J080AA" FP-CGA3E2C0G1H331J080AA_0603-MFG 64.807,133.082 r0 top value=330pF (schematic designator C242)
C242_L2 "CGA3E2C0G1H331J080AA" FP-CGA3E2C0G1H331J080AA_0603-MFG 148.807,118.082 r0 top value=330pF (schematic designator C242)
C242_L3 "CGA3E2C0G1H331J080AA" FP-CGA3E2C0G1H331J080AA_0603-MFG 232.807,90.082 r0 top value=330pF (schematic designator C242)
C242_N "CGA3E2C0G1H331J080AA" FP-CGA3E2C0G1H331J080AA_0603-MFG 103.418,33.807 r90 top value=330pF (schematic designator C242)
C243_L1 "06033C104JAT2A" 0603 34.073,116.955 r270 top value=0.1uF (schematic designator C243)
C243_L2 "06033C104JAT2A" 0603 118.073,101.955 r270 top value=0.1uF (schematic designator C243)
C243_L3 "06033C104JAT2A" 0603 202.073,73.955 r270 top value=0.1uF (schematic designator C243)
C243_N "06033C104JAT2A" 0603 119.545,3.073 r0 top value=0.1uF (schematic designator C243)
C244_L1 "06033C104JAT2A" 0603 38.076,133.907 r270 top value=0.1uF (schematic designator C244)
C244_L2 "06033C104JAT2A" 0603 122.076,118.907 r270 top value=0.1uF (schematic designator C244)
C244_L3 "06033C104JAT2A" 0603 206.076,90.907 r270 top value=0.1uF (schematic designator C244)
C244_N "06033C104JAT2A" 0603 102.593,7.076 r0 top value=0.1uF (schematic designator C244)
C245_L1 "CGA3E2C0G1H331J080AA" FP-CGA3E2C0G1H331J080AA_0603-MFG 44.3,165.75 r0 bottom value=330pF (schematic designator C245)
C245_L2 "CGA3E2C0G1H331J080AA" FP-CGA3E2C0G1H331J080AA_0603-MFG 128.3,150.75 r0 bottom value=330pF (schematic designator C245)
C245_L3 "CGA3E2C0G1H331J080AA" FP-CGA3E2C0G1H331J080AA_0603-MFG 212.3,122.75 r0 bottom value=330pF (schematic designator C245)
C245_N "CGA3E2C0G1H331J080AA" FP-CGA3E2C0G1H331J080AA_0603-MFG 70.75,13.3 r90 bottom value=330pF (schematic designator C245)
C246_L1 "CGA3E2C0G1H331J080AA" FP-CGA3E2C0G1H331J080AA_0603-MFG 36.111,133.882 r270 top value=330pF (schematic designator C246)
C246_L2 "CGA3E2C0G1H331J080AA" FP-CGA3E2C0G1H331J080AA_0603-MFG 120.111,118.882 r270 top value=330pF (schematic designator C246)
C246_L3 "CGA3E2C0G1H331J080AA" FP-CGA3E2C0G1H331J080AA_0603-MFG 204.111,90.882 r270 top value=330pF (schematic designator C246)
C246_N "CGA3E2C0G1H331J080AA" FP-CGA3E2C0G1H331J080AA_0603-MFG 102.518,5.111 r0 top value=330pF (schematic designator C246)
C247_L1 "06033C104JAT2A" 0603 42.75,169.5 r0 bottom value=0.1uF (schematic designator C247)
C247_L2 "06033C104JAT2A" 0603 126.75,154.5 r0 bottom value=0.1uF (schematic designator C247)
C247_L3 "06033C104JAT2A" 0603 210.75,126.5 r0 bottom value=0.1uF (schematic designator C247)
C247_N "06033C104JAT2A" 0603 67,11.75 r90 bottom value=0.1uF (schematic designator C247)
C248_L1 "CGA3E2C0G1H331J080AA" FP-CGA3E2C0G1H331J080AA_0603-MFG 37.175,117.309 r90 top value=330pF (schematic designator C248)
C248_L2 "CGA3E2C0G1H331J080AA" FP-CGA3E2C0G1H331J080AA_0603-MFG 121.175,102.309 r90 top value=330pF (schematic designator C248)
C248_L3 "CGA3E2C0G1H331J080AA" FP-CGA3E2C0G1H331J080AA_0603-MFG 205.175,74.309 r90 top value=330pF (schematic designator C248)
C248_N "CGA3E2C0G1H331J080AA" FP-CGA3E2C0G1H331J080AA_0603-MFG 119.191,6.175 r180 top value=330pF (schematic designator C248)
C249_L1 "GRT31CR61H106KE01L" 1206_180 36.111,136.783 r180 top value=10uF (schematic designator C249)
C249_L2 "GRT31CR61H106KE01L" 1206_180 120.111,121.783 r180 top value=10uF (schematic designator C249)
C249_L3 "GRT31CR61H106KE01L" 1206_180 204.111,93.783 r180 top value=10uF (schematic designator C249)
C249_N "GRT31CR61H106KE01L" 1206_180 99.717,5.111 r270 top value=10uF (schematic designator C249)
C250_L1 "885012205063" WCAP-CSGP_0402_L1W0.5H0.5 42.456,131.907 r0 top (schematic designator C250)
C250_L2 "885012205063" WCAP-CSGP_0402_L1W0.5H0.5 126.456,116.907 r0 top (schematic designator C250)
C250_L3 "885012205063" WCAP-CSGP_0402_L1W0.5H0.5 210.456,88.907 r0 top (schematic designator C250)
C250_N "885012205063" WCAP-CSGP_0402_L1W0.5H0.5 104.593,11.456 r90 top (schematic designator C250)
C251_L1 "GRM21BZ71A226ME15L" 0805_HV 41.203,133.573 r180 top value=22uF (schematic designator C251)
C251_L2 "GRM21BZ71A226ME15L" 0805_HV 125.203,118.573 r180 top value=22uF (schematic designator C251)
C251_L3 "GRM21BZ71A226ME15L" 0805_HV 209.203,90.573 r180 top value=22uF (schematic designator C251)
C251_N "GRM21BZ71A226ME15L" 0805_HV 102.927,10.203 r270 top value=22uF (schematic designator C251)
C252_L1 "06033C104JAT2A" 0603 34.561,133.998 r90 top value=0.1uF (schematic designator C252)
C252_L2 "06033C104JAT2A" 0603 118.561,118.998 r90 top value=0.1uF (schematic designator C252)
C252_L3 "06033C104JAT2A" 0603 202.561,90.998 r90 top value=0.1uF (schematic designator C252)
C252_N "06033C104JAT2A" 0603 102.502,3.561 r180 top value=0.1uF (schematic designator C252)
C253_L1 "CGA3E2C0G1H331J080AA" FP-CGA3E2C0G1H331J080AA_0603-MFG 40.228,117.755 r90 top value=330pF (schematic designator C253)
C253_L2 "CGA3E2C0G1H331J080AA" FP-CGA3E2C0G1H331J080AA_0603-MFG 124.228,102.755 r90 top value=330pF (schematic designator C253)
C253_L3 "CGA3E2C0G1H331J080AA" FP-CGA3E2C0G1H331J080AA_0603-MFG 208.228,74.755 r90 top value=330pF (schematic designator C253)
C253_N "CGA3E2C0G1H331J080AA" FP-CGA3E2C0G1H331J080AA_0603-MFG 118.745,9.228 r180 top value=330pF (schematic designator C253)
C254_L1 "GRM21BZ71A226ME15L" 0805_HV 46,117.655 r90 top value=22uF (schematic designator C254)
C254_L2 "GRM21BZ71A226ME15L" 0805_HV 130,102.655 r90 top value=22uF (schematic designator C254)
C254_L3 "GRM21BZ71A226ME15L" 0805_HV 214,74.655 r90 top value=22uF (schematic designator C254)
C254_N "GRM21BZ71A226ME15L" 0805_HV 118.845,15 r180 top value=22uF (schematic designator C254)
C255_L1 "GRM21BZ71A226ME15L" 0805_HV 42.754,116.659 r0 top value=22uF (schematic designator C255)
C255_L2 "GRM21BZ71A226ME15L" 0805_HV 126.754,101.659 r0 top value=22uF (schematic designator C255)
C255_L3 "GRM21BZ71A226ME15L" 0805_HV 210.754,73.659 r0 top value=22uF (schematic designator C255)
C255_N "GRM21BZ71A226ME15L" 0805_HV 119.841,11.754 r90 top value=22uF (schematic designator C255)
C256_L1 "885012205051" WCAP-CSGP_0402_L1W0.5H0.5 42.153,118.432 r180 top (schematic designator C256)
C256_L2 "885012205051" WCAP-CSGP_0402_L1W0.5H0.5 126.153,103.432 r180 top (schematic designator C256)
C256_L3 "885012205051" WCAP-CSGP_0402_L1W0.5H0.5 210.153,75.432 r180 top (schematic designator C256)
C256_N "885012205051" WCAP-CSGP_0402_L1W0.5H0.5 118.068,11.153 r270 top (schematic designator C256)
C257 "B58043E5254M052" FP-B58043E5254M052_2220-MFG 8.746,236.141 r0 bottom value=250nF
C258 "B58043E5254M052" FP-B58043E5254M052_2220-MFG 8.75,229.271 r0 bottom value=250nF
C259 "EEU-FM1E101" FM_630x1120 149.65,10.9 r0 top value=100uF
C260 "EEU-FM1E101" FM_630x1120 157.05,3.6 r0 top value=100uF
C261 "GRM155R71E104KE14D" 0402L 206.321,5.628 r180 top value=0.1uF
C262 "CGA3E2C0G1H331J080AA" FP-CGA3E2C0G1H331J080AA_0603-MFG 266.1,56.5 r0 top value=330pF
C263 "CGA2B2C0G1H102J050BA" 0402L 235.925,33.95 r90 top value=1000pF
D1 "KG DELLS1.22-JGKH-24" "FP-KG DELLS1.22-JGKH-24_0603-MFG" 185.5,45.5 r0 top
D2 "KG DELLS1.22-JGKH-24" "FP-KG DELLS1.22-JGKH-24_0603-MFG" 185.4,43.4 r0 top
D3 "B160-13-F" SMA 287.4,211.4 r270 top value=60V
D4 "150060VS75000" WL-SMCW_GREEN 168.682,4.596 r270 top value=Green
D5 "B330A-13-F" SMA 173.119,5.34 r180 top value=30V
D6 "150060VS75000" WL-SMCW_GREEN 160.083,20.625 r0 top value=Green
D7_L1 "ZGL41-180A-E3/96" FP-ZGL41-180A-E3/96_GL41-MFG 95.113,162.75 r270 top (schematic designator D7)
D7_L2 "ZGL41-180A-E3/96" FP-ZGL41-180A-E3/96_GL41-MFG 179.113,147.75 r270 top (schematic designator D7)
D7_L3 "ZGL41-180A-E3/96" FP-ZGL41-180A-E3/96_GL41-MFG 263.113,119.75 r270 top (schematic designator D7)
D7_N "ZGL41-180A-E3/96" FP-ZGL41-180A-E3/96_GL41-MFG 73.75,64.113 r0 top (schematic designator D7)
D8_L1 "ZGL41-180A-E3/96" FP-ZGL41-180A-E3/96_GL41-MFG 95.147,148.25 r270 top (schematic designator D8)
D8_L2 "ZGL41-180A-E3/96" FP-ZGL41-180A-E3/96_GL41-MFG 179.147,133.25 r270 top (schematic designator D8)
D8_L3 "ZGL41-180A-E3/96" FP-ZGL41-180A-E3/96_GL41-MFG 263.147,105.25 r270 top (schematic designator D8)
D8_N "ZGL41-180A-E3/96" FP-ZGL41-180A-E3/96_GL41-MFG 88.25,64.147 r0 top (schematic designator D8)
D9_L1 "ZGL41-180A-E3/96" FP-ZGL41-180A-E3/96_GL41-MFG 95.172,155.446 r270 top (schematic designator D9)
D9_L2 "ZGL41-180A-E3/96" FP-ZGL41-180A-E3/96_GL41-MFG 179.172,140.446 r270 top (schematic designator D9)
D9_L3 "ZGL41-180A-E3/96" FP-ZGL41-180A-E3/96_GL41-MFG 263.172,112.446 r270 top (schematic designator D9)
D9_N "ZGL41-180A-E3/96" FP-ZGL41-180A-E3/96_GL41-MFG 81.054,64.172 r0 top (schematic designator D9)
D10_L1 "APG1608SURKC/T" FP-APG1608SURKC_T_0603-MFG 91.45,138.303 r0 top (schematic designator D10)
D10_L2 "APG1608SURKC/T" FP-APG1608SURKC_T_0603-MFG 175.45,123.303 r0 top (schematic designator D10)
D10_L3 "APG1608SURKC/T" FP-APG1608SURKC_T_0603-MFG 259.45,95.303 r0 top (schematic designator D10)
D10_N "APG1608SURKC/T" FP-APG1608SURKC_T_0603-MFG 98.197,60.45 r90 top (schematic designator D10)
D11_L1 "APG1608SURKC/T" FP-APG1608SURKC_T_0603-MFG 75.28,138.732 r0 top (schematic designator D11)
D11_L2 "APG1608SURKC/T" FP-APG1608SURKC_T_0603-MFG 159.28,123.732 r0 top (schematic designator D11)
D11_L3 "APG1608SURKC/T" FP-APG1608SURKC_T_0603-MFG 243.28,95.732 r0 top (schematic designator D11)
D11_N "APG1608SURKC/T" FP-APG1608SURKC_T_0603-MFG 97.768,44.28 r90 top (schematic designator D11)
D12_L1 "APG1608SURKC/T" FP-APG1608SURKC_T_0603-MFG 51.764,138.624 r0 top (schematic designator D12)
D12_L2 "APG1608SURKC/T" FP-APG1608SURKC_T_0603-MFG 135.764,123.624 r0 top (schematic designator D12)
D12_L3 "APG1608SURKC/T" FP-APG1608SURKC_T_0603-MFG 219.764,95.624 r0 top (schematic designator D12)
D12_N "APG1608SURKC/T" FP-APG1608SURKC_T_0603-MFG 97.876,20.764 r90 top (schematic designator D12)
D13_L1 "ZGL41-180A-E3/96" FP-ZGL41-180A-E3/96_GL41-MFG 40.403,149.6 r90 top (schematic designator D13)
D13_L2 "ZGL41-180A-E3/96" FP-ZGL41-180A-E3/96_GL41-MFG 124.403,134.6 r90 top (schematic designator D13)
D13_L3 "ZGL41-180A-E3/96" FP-ZGL41-180A-E3/96_GL41-MFG 208.403,106.6 r90 top (schematic designator D13)
D13_N "ZGL41-180A-E3/96" FP-ZGL41-180A-E3/96_GL41-MFG 86.9,9.403 r180 top (schematic designator D13)
D14_L1 "ZGL41-180A-E3/96" FP-ZGL41-180A-E3/96_GL41-MFG 40.403,162.788 r90 top (schematic designator D14)
D14_L2 "ZGL41-180A-E3/96" FP-ZGL41-180A-E3/96_GL41-MFG 124.403,147.788 r90 top (schematic designator D14)
D14_L3 "ZGL41-180A-E3/96" FP-ZGL41-180A-E3/96_GL41-MFG 208.403,119.788 r90 top (schematic designator D14)
D14_N "ZGL41-180A-E3/96" FP-ZGL41-180A-E3/96_GL41-MFG 73.712,9.403 r180 top (schematic designator D14)
D15_L1 "ZGL41-180A-E3/96" FP-ZGL41-180A-E3/96_GL41-MFG 40.403,156.116 r90 top (schematic designator D15)
D15_L2 "ZGL41-180A-E3/96" FP-ZGL41-180A-E3/96_GL41-MFG 124.403,141.116 r90 top (schematic designator D15)
D15_L3 "ZGL41-180A-E3/96" FP-ZGL41-180A-E3/96_GL41-MFG 208.403,113.116 r90 top (schematic designator D15)
D15_N "ZGL41-180A-E3/96" FP-ZGL41-180A-E3/96_GL41-MFG 80.384,9.403 r180 top (schematic designator D15)
D16_L1 "APG1608SURKC/T" FP-APG1608SURKC_T_0603-MFG 35.25,138.784 r0 top (schematic designator D16)
D16_L2 "APG1608SURKC/T" FP-APG1608SURKC_T_0603-MFG 119.25,123.784 r0 top (schematic designator D16)
D16_L3 "APG1608SURKC/T" FP-APG1608SURKC_T_0603-MFG 203.25,95.784 r0 top (schematic designator D16)
D16_N "APG1608SURKC/T" FP-APG1608SURKC_T_0603-MFG 97.716,4.25 r90 top (schematic designator D16)
D17 "B160-13-F" SMA 211.9,3.8 r180 top value=60V
D18 "150060VS75000" WL-SMCW_GREEN 286.25,15.55 r90 top value=Green
F1 "SF-3812F2500T-2" FP-SF-3812F2500T-2_SMD2-MFG 247,274 r90 top
F2 "SF-3812F2500T-2" FP-SF-3812F2500T-2_SMD2-MFG 233,274 r90 top
F3 "SF-3812F2500T-2" FP-SF-3812F2500T-2_SMD2-MFG 217,274 r90 top
F4 "SF-3812F2500T-2" FP-SF-3812F2500T-2_SMD2-MFG 271.5,275 r180 top
FB1 "MH1608-601Y" FP-MH1608-601Y_0603-MFG 198.5,34.2 r0 top
FB2 "MH1608-601Y" FP-MH1608-601Y_0603-MFG 100.5,236.7 r270 top
FB3 "MH1608-601Y" FP-MH1608-601Y_0603-MFG 112,229.9 r180 top
FB4 "MH1608-601Y" FP-MH1608-601Y_0603-MFG 199,205 r270 top
FB5 "MH1608-601Y" FP-MH1608-601Y_0603-MFG 264.7,46.8 r0 top
FB6 "MH1608-601Y" FP-MH1608-601Y_0603-MFG 44.6,106.5 r180 top
FB7 "MH1608-601Y" FP-MH1608-601Y_0603-MFG 139,247.2 r270 top
FB8 "MH1608-601Y" FP-MH1608-601Y_0603-MFG 125,247.1 r270 top
FB9 "MH1608-601Y" FP-MH1608-601Y_0603-MFG 113.8,247.2 r270 top
FB10 "MH1608-601Y" FP-MH1608-601Y_0603-MFG 102.3,262.896 r180 top
FB11 "MH1608-601Y" FP-MH1608-601Y_0603-MFG 178.4,78.3 r180 top
FB12 "BLM15EX331SN1D" FP-BLM15EX331SN1D_0402-MFG 290.8,38 r180 top
FB13 "BLM15EX331SN1D" FP-BLM15EX331SN1D_0402-MFG 291.1,35.1 r270 top
FB14_L1 "MH1608-601Y" FP-MH1608-601Y_0603-MFG 64.989,115.842 r0 top (schematic designator FB14)
FB14_L2 "MH1608-601Y" FP-MH1608-601Y_0603-MFG 148.989,100.842 r0 top (schematic designator FB14)
FB14_L3 "MH1608-601Y" FP-MH1608-601Y_0603-MFG 232.989,72.842 r0 top (schematic designator FB14)
FB14_N "MH1608-601Y" FP-MH1608-601Y_0603-MFG 120.658,33.989 r90 top (schematic designator FB14)
FB15_L1 "MH1608-601Y" FP-MH1608-601Y_0603-MFG 65.1,136.184 r180 top (schematic designator FB15)
FB15_L2 "MH1608-601Y" FP-MH1608-601Y_0603-MFG 149.1,121.184 r180 top (schematic designator FB15)
FB15_L3 "MH1608-601Y" FP-MH1608-601Y_0603-MFG 233.1,93.184 r180 top (schematic designator FB15)
FB15_N "MH1608-601Y" FP-MH1608-601Y_0603-MFG 100.316,34 r270 top (schematic designator FB15)
FB16 "MH1608-601Y" FP-MH1608-601Y_0603-MFG 262.6,64.4 r180 top
FB17 "BLM15EX331SN1D" FP-BLM15EX331SN1D_0402-MFG 287.75,19.55 r0 top
FB18 "BLM15EX331SN1D" FP-BLM15EX331SN1D_0402-MFG 288.25,16.05 r0 top
FID1 "Fiducial" Fiducial10-20 297,13.4 r0 top
FID2 "Fiducial" Fiducial10-20 47.8,298.1 r0 top
FID3 "Fiducial" Fiducial10-20 181.4,239.2 r0 top
J1 "618009231121" Wurth_618009231121 272.5,0 r270 top
J2 "FCR7350R" Cliff_FCR7350R 7,290 r180 top
J3 "FCR7350N" FP-FCR7350N_CONN_BANANA_JACK-MFG 247,299 r270 top
J4 "0022111031" FP-0022111031_HDR3-MFG 232.8,3.8 r180 top
J5 "FCR7350N" FP-FCR7350N_CONN_BANANA_JACK-MFG 227,299 r270 top
J6 "0022111031" FP-0022111031_HDR3-MFG 221.3,3.8 r180 top
J7 "FCR7350N" FP-FCR7350N_CONN_BANANA_JACK-MFG 207,299 r270 top
J8 "FCR7350B" Cliff_FCR7350B 267.08,288.64 r180 top
J9 "FCR7350B" Cliff_FCR7350B 22,290 r180 top
J10 "FCR7350G" FP-FCR7350G_CONN_BANANA_JACK-MFG 293,299 r270 top
J11 "TSM-102-01-T-SV-P-TR" Samtec_TSM-102-01-T-SV-P-TR 252.4,11.7 r270 top
J12 "HSEC8-160-01-L-DV-A-BL" controlCARD-120HSEC 225.193,43.722 r180 top
J13 "TSW-112-07-G-S" TSW-112-07-G-S 201.5,19.5 r0 top
J14 "TSM-102-01-T-SV-P-TR" Samtec_TSM-102-01-T-SV-P-TR 184.538,9.425 r180 top
J15 "TSM-102-01-T-SV-P-TR" Samtec_TSM-102-01-T-SV-P-TR 163.479,7.898 r180 top
J16 "PJ-002AH-SMT-TR" CUI_PJ-002AH-SMT 196.2,8.2 r90 top
J17 "TSM-102-01-T-SV-P-TR" Samtec_TSM-102-01-T-SV-P-TR 175.751,23.754 r180 top
J18 "TSM-102-01-T-SV-P-TR" Samtec_TSM-102-01-T-SV-P-TR 157.833,15.475 r270 top
J21 "0022111031" FP-0022111031_HDR3-MFG 244.2,3.8 r180 top
L1 "B181179 V0 D6938" "FP-B181179 V0 D6938_PTH8-MFG" 64,207 r90 top value=87uH
L2 "B181179 V0 D6938" "FP-B181179 V0 D6938_PTH8-MFG" 148,192 r90 top value=87uH
L3 "ACT45B-101-2P-TL003" FP-ACT45B-101-2P-TL003_SMT_4MM5_3MM2-MFG 258.5,18.475 r270 top
L5 "B181179 V0 D6938" "FP-B181179 V0 D6938_PTH8-MFG" 232,164 r90 top value=87uH
L6 "B181179 V0 D6938" "FP-B181179 V0 D6938_PTH8-MFG" 29.165,38.25 r180 top value=87uH
L7 "74479763222" WE-PMI_0603_L1.6W0.8H0.8 98.1,245 r0 top
L8 "74479763222" WE-PMI_0603_L1.6W0.8H0.8 91.7,90.5 r180 top
L9 "74479763222" WE-PMI_0603_L1.6W0.8H0.8 94.8,108.7 r180 top
L10_L1 "SDR0302-150ML" SDR0302 101,133.082 r270 top value=15uH (schematic designator L10)
L10_L2 "SDR0302-150ML" SDR0302 185,118.082 r270 top value=15uH (schematic designator L10)
L10_L3 "SDR0302-150ML" SDR0302 269,90.082 r270 top value=15uH (schematic designator L10)
L10_N "SDR0302-150ML" SDR0302 103.418,70 r0 top value=15uH (schematic designator L10)
L11_L1 "74479763222" WE-PMI_0603_L1.6W0.8H0.8 98.263,114.658 r0 top (schematic designator L11)
L11_L2 "74479763222" WE-PMI_0603_L1.6W0.8H0.8 182.263,99.658 r0 top (schematic designator L11)
L11_L3 "74479763222" WE-PMI_0603_L1.6W0.8H0.8 266.263,71.658 r0 top (schematic designator L11)
L11_N "74479763222" WE-PMI_0603_L1.6W0.8H0.8 121.842,67.263 r90 top (schematic designator L11)
L12 "B181178 V0 D6937" "FP-B181178 V0 D6937_PTH8-MFG" 170.3,271.1 r175 top
L12_L1 "SDR0302-150ML" SDR0302 84.173,133.898 r270 top value=15uH (schematic designator L12)
L12_L2 "SDR0302-150ML" SDR0302 168.173,118.898 r270 top value=15uH (schematic designator L12)
L12_L3 "SDR0302-150ML" SDR0302 252.173,90.898 r270 top value=15uH (schematic designator L12)
L12_N "SDR0302-150ML" SDR0302 102.602,53.173 r0 top value=15uH (schematic designator L12)
L13_L1 "74479763222" WE-PMI_0603_L1.6W0.8H0.8 81.894,114.934 r0 top (schematic designator L13)
L13_L2 "74479763222" WE-PMI_0603_L1.6W0.8H0.8 165.894,99.934 r0 top (schematic designator L13)
L13_L3 "74479763222" WE-PMI_0603_L1.6W0.8H0.8 249.894,71.934 r0 top (schematic designator L13)
L13_N "74479763222" WE-PMI_0603_L1.6W0.8H0.8 121.566,50.894 r90 top (schematic designator L13)
L14_L1 "SDR0302-150ML" SDR0302 61.225,134.216 r270 top value=15uH (schematic designator L14)
L14_L2 "SDR0302-150ML" SDR0302 145.225,119.216 r270 top value=15uH (schematic designator L14)
L14_L3 "SDR0302-150ML" SDR0302 229.225,91.216 r270 top value=15uH (schematic designator L14)
L14_N "SDR0302-150ML" SDR0302 102.284,30.225 r0 top value=15uH (schematic designator L14)
L15_L1 "74479763222" WE-PMI_0603_L1.6W0.8H0.8 58.21,114.842 r0 top (schematic designator L15)
L15_L2 "74479763222" WE-PMI_0603_L1.6W0.8H0.8 142.21,99.842 r0 top (schematic designator L15)
L15_L3 "74479763222" WE-PMI_0603_L1.6W0.8H0.8 226.21,71.842 r0 top (schematic designator L15)
L15_N "74479763222" WE-PMI_0603_L1.6W0.8H0.8 121.658,27.21 r90 top (schematic designator L15)
L16_L1 "SDR0302-150ML" SDR0302 44.994,134.191 r270 top value=15uH (schematic designator L16)
L16_L2 "SDR0302-150ML" SDR0302 128.994,119.191 r270 top value=15uH (schematic designator L16)
L16_L3 "SDR0302-150ML" SDR0302 212.994,91.191 r270 top value=15uH (schematic designator L16)
L16_N "SDR0302-150ML" SDR0302 102.309,13.994 r0 top value=15uH (schematic designator L16)
L17_L1 "74479763222" WE-PMI_0603_L1.6W0.8H0.8 45.2,114.917 r0 top (schematic designator L17)
L17_L2 "74479763222" WE-PMI_0603_L1.6W0.8H0.8 129.2,99.917 r0 top (schematic designator L17)
L17_L3 "74479763222" WE-PMI_0603_L1.6W0.8H0.8 213.2,71.917 r0 top (schematic designator L17)
L17_N "74479763222" WE-PMI_0603_L1.6W0.8H0.8 121.583,14.2 r90 top (schematic designator L17)
L19 "B181178 V0 D6937" "FP-B181178 V0 D6937_PTH8-MFG" 62,271 r135 top
LBL1 "THT-14-423-10" Label_650x200 297.2,93.6 r270 top
Logo1 "CE Mark" CE_Mark_5mm 296.9,76.2 r90 top
Logo2 "Texas Instruments" TI_Stacked_Overlay_Small 147.6,42.4 r0 top
Logo3 "FCC disclaimer" FCC_disclaimer 291.6,88.6 r90 top
Logo4 "WEEE logo" WEEE_Minimum 296.7,107.3 r0 top
MP1 "9774030960R" FP-9774030960R_SPACER-MFG#1 277,80 r180 bottom
MP2 "9774030960R" FP-9774030960R_SPACER-MFG#1 105.5,192.5 r180 bottom
MP3 "9774030960R" FP-9774030960R_SPACER-MFG#1 110,125 r180 bottom
MP4 "9774030960R" FP-9774030960R_SPACER-MFG#2 39,296 r180 bottom
MP5 "9774030960R" FP-9774030960R_SPACER-MFG#1 66,100 r180 bottom
MP6 "9774030960R" FP-9774030960R_SPACER-MFG#2 282,296 r180 bottom
MP7 "9774030960R" FP-9774030960R_SPACER-MFG#1 295,155 r180 bottom
MP8 "9774030960R" FP-9774030960R_SPACER-MFG#1 50,5 r270 bottom
MP9 "9774030960R" FP-9774030960R_SPACER-MFG#1 5,5 r180 bottom
MP10 "9774030960R" FP-9774030960R_SPACER-MFG#1 295,5 r180 bottom
MP10 "9774030960R" FP-9774030960R_SPACER-MFG#1 193,296 r180 bottom
MP11 "9774030960R" FP-9774030960R_SPACER-MFG#1 190,178 r180 bottom
MP12 "9774030960R" FP-9774030960R_SPACER-MFG#1 191,93 r90 bottom
MP13 "9774030960R" FP-9774030960R_SPACER-MFG#1 184,216 r180 bottom
MP14 "9774030960R" FP-9774030960R_SPACER-MFG#1 5,139 r180 bottom
MP15 "9774030960R" FP-9774030960R_SPACER-MFG#1 138,5 r180 bottom
Q1 "CSD17571Q2" DQK0006C 288.905,206.65 r0 top value=30V
Q2 "CSD17571Q2" DQK0006C 166.382,13.809 r90 top value=30V
Q3 "CSD17571Q2" DQK0006C 206.45,3.443 r180 top value=30V
R1 "CRCW1206510KJNEA" 1206 36.323,53 r90 bottom value=510k
R2 "CRCW1206510KJNEA" 1206 32.248,53 r90 bottom value=510k
R3 "CRCW1206510KJNEA" 1206 28.248,53 r90 bottom value=510k
R4 "CRCW1206510KJNEA" 1206 36.323,47.496 r90 bottom value=510k
R5 "CRCW1206510KJNEA" 1206 32.248,47.496 r90 bottom value=510k
R6 "CRCW1206510KJNEA" 1206 28.248,47.496 r90 bottom value=510k
R7 "CRCW1206510KJNEA" 1206 36.323,42.05 r90 bottom value=510k
R8 "CRCW1206510KJNEA" 1206 32.248,42 r90 bottom value=510k
R9 "CRCW1206510KJNEA" 1206 28.248,41.95 r90 bottom value=510k
R10 "CRCW1206510KJNEA" 1206 36.323,36.05 r90 bottom value=510k
R11 "CRCW1206510KJNEA" 1206 32.248,36.05 r90 bottom value=510k
R12 "CRCW1206510KJNEA" 1206 28.248,36.05 r90 bottom value=510k
R13 "CRCW1206510KJNEA" 1206 36.323,30.496 r90 bottom value=510k
R14 "CRCW1206510KJNEA" 1206 32.248,30.496 r90 bottom value=510k
R15 "CRCW1206510KJNEA" 1206 28.248,30.496 r90 bottom value=510k
R16 "CRCW1206510KJNEA" 1206 36.323,24.946 r90 bottom value=510k
R17 "CRCW1206510KJNEA" 1206 32.248,24.946 r90 bottom value=510k
R18 "CRCW1206510KJNEA" 1206 28.248,25 r90 bottom value=510k
R19 "ERJ-2RKF33R0X" 0402L 192.9,80.3 r90 top value=33.0
R20 "RCS06030000Z0EA" 0603 247.8,51.3 r90 top value=0
R21 "RCS06030000Z0EA" 0603 246,51.3 r90 top value=0
R22 "RCS06030000Z0EA" 0603 248.4,36 r270 top value=0
R23 "RCS06030000Z0EA" 0603 244.1,54.2 r90 top value=0
R24 "RCS06030000Z0EA" 0603 246.7,36 r270 top value=0
R25 "ERJ-2RKF33R0X" 0402L 242.9,50.3 r270 top value=33.0
R26 "RCS06030000Z0EA" 0603 242.1,54.2 r90 top value=0
R27 "RCS06030000Z0EA" 0603 245.1,36 r270 top value=0
R28 "RCS06030000Z0EA" 0603 243.5,36 r270 top value=0
R29 "ERJ-2RKF33R0X" 0402L 241.1,50.4 r270 top value=33.0
R30 "ERJ-2RKF33R0X" 0402L 242.2,36.6 r270 top value=33.0
R31 "RCS06030000Z0EA" 0603 239.9,54.2 r90 top value=0
R32 "RCS06030000Z0EA" 0603 240.9,36 r90 top value=0
R33 "RCS06030000Z0EA" 0603 238.3,50.8 r90 top value=0
R34 "RCS06030000Z0EA" 0603 239.2,36 r90 top value=0
R35 "RCS06030000Z0EA" 0603 237.5,36 r90 top value=0
R36 "RCS06030000Z0EA" 0603 236.8,54.1 r90 top value=0
R37 "RCS06030000Z0EA" 0603 235.5,50.8 r90 top value=0
R38 "RCS06030000Z0EA" 0603 235.925,37.15 r90 top value=0
R39 "RCS06030000Z0EA" 0603 234.1,54.1 r90 top value=0
R40 "RCS06030000Z0EA" 0603 232.9,50.8 r90 top value=0
R41 "RCS06030000Z0EA" 0603 234.1,37.1 r90 top value=0
R42 "RCS06030000Z0EA" 0603 232.1,37.4 r90 top value=0
R43 "ERJ-2RKF33R0X" 0402L 229.7,50 r270 top value=33.0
